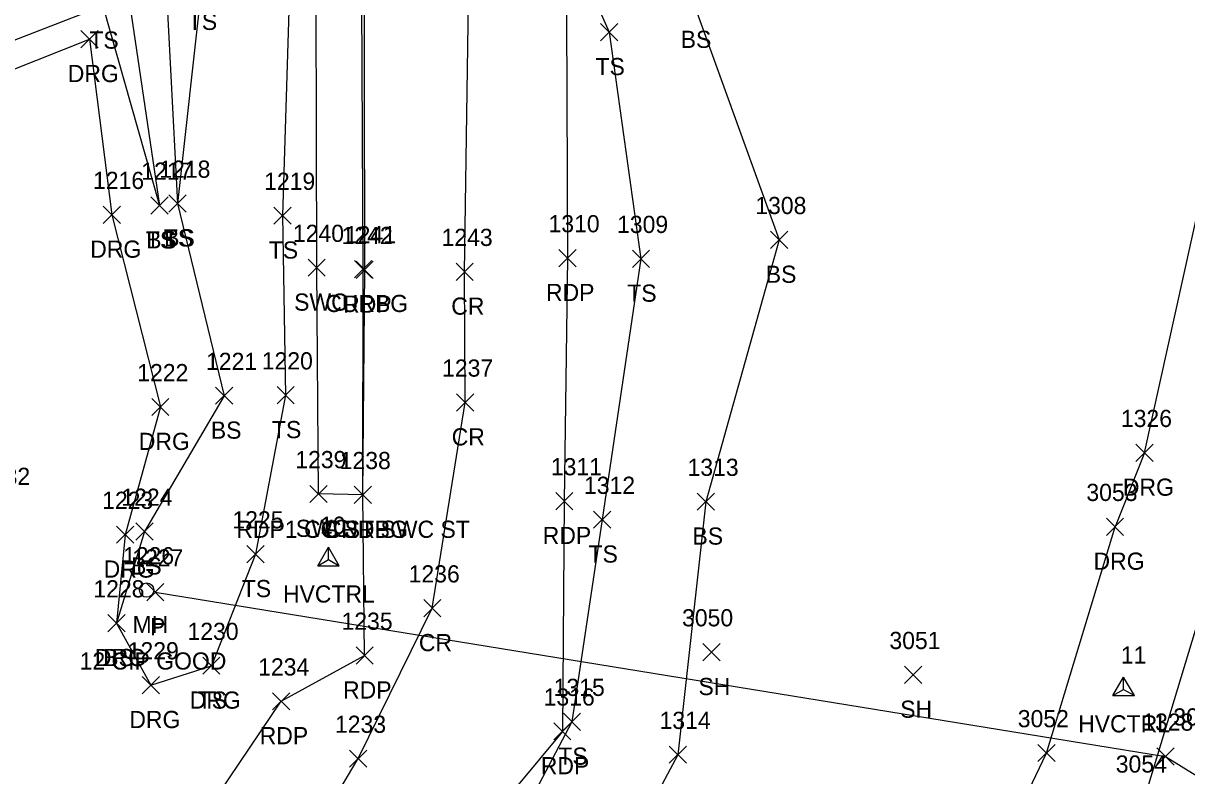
# Model space of a CAD drawing. Extents: x 49137 to 50946, y 9590 to 10709.
# Drawn here: x 49926.3 to 50061.8, y 9806.1 to 9893.7 of the extents above; entities that cross this region are included whole.
import ezdxf

# ---------------------------------------------------------------- set-up
doc = ezdxf.new("R2010")
doc.units = 0
for name, color, linetype in [('C_A', 7, 'Continuous'), ('C_I', 7, 'Continuous'), ('CPSM', 7, 'Continuous'), ('D_A', 7, 'Continuous'), ('D_C', 7, 'Continuous'), ('D_I', 7, 'Continuous'), ('D_TIC', 7, 'Continuous'), ('DCP', 7, 'Continuous'), ('L_A', 7, 'Continuous'), ('L_I', 7, 'Continuous'), ('L_TIC', 7, 'Continuous'), ('LELB', 7, 'Continuous'), ('P_A', 7, 'Continuous'), ('P_I', 7, 'Continuous'), ('P_TIC', 7, 'Continuous'), ('PET', 7, 'Continuous'), ('PRC', 7, 'Continuous'), ('R_A', 7, 'Continuous'), ('R_I', 7, 'Continuous'), ('R_TIC', 7, 'Continuous'), ('RC', 7, 'Continuous'), ('RDG', 7, 'Continuous'), ('RSW', 7, 'Continuous'), ('U_A', 7, 'Continuous'), ('U_I', 7, 'Continuous'), ('UUMH', 7, 'Continuous')]:
    doc.layers.add(name, color=color, linetype=linetype)

msp = doc.modelspace()

# ---------------------------------------------------------------- linework, layer by layer
at = {"layer": 'CPSM'}
for p, q in [((49960.61, 9830.56), (49961.86, 9832.72)), ((49963.11, 9830.56), (49961.86, 9832.72)), ((49961.86, 9831.28), (49961.86, 9832.72)), ((49960.61, 9830.56), (49961.86, 9831.28)), ((49960.61, 9830.56), (49963.11, 9830.56)), ((49961.86, 9831.28), (49961.86, 9831.28)), ((49961.86, 9831.28), (49963.11, 9830.56)), ((50053.22, 9815.45), (50054.47, 9817.61)), ((50055.72, 9815.45), (50054.47, 9817.61)), ((50054.47, 9816.17), (50054.47, 9817.61)), ((50053.22, 9815.45), (50054.47, 9816.17)), ((50054.47, 9816.17), (50054.47, 9816.17)), ((50054.47, 9816.17), (50055.72, 9815.45)), ((50053.22, 9815.45), (50055.72, 9815.45))]:
    msp.add_line(p, q, dxfattribs=at)
at = {"layer": 'D_TIC'}
for points in [[(49940.69, 9826.48), (49942.69, 9828.48)], [(49942.69, 9826.48), (49940.69, 9828.48)], [(50058.34, 9807.37), (50060.34, 9809.37)], [(50060.34, 9807.37), (50058.34, 9809.37)]]:
    msp.add_lwpolyline(points, dxfattribs=at)
at = {"layer": 'DCP'}
msp.add_lwpolyline([(49941.69, 9827.48), (50059.34, 9808.37), (50181.4, 9733.09), (50281.74, 9743.29), (50422.72, 9892.52), (50122.34, 10663.61), (50179.93, 10552.61), (50179.64, 10394.45), (50122.34, 10285.07), (50121.56, 10284.35)], dxfattribs=at)
at = {"layer": 'L_TIC'}
for points in [[(49993.55, 9891.66), (49995.55, 9893.66)], [(49995.55, 9891.66), (49993.55, 9893.66)], [(49941.19, 9871.49), (49943.19, 9873.49)], [(49943.19, 9871.49), (49941.19, 9873.49)], [(49941.19, 9871.49), (49943.19, 9873.49)], [(49943.19, 9871.49), (49941.19, 9873.49)], [(49943.28, 9871.72), (49945.28, 9873.72)], [(49945.28, 9871.72), (49943.28, 9873.72)], [(49943.28, 9871.72), (49945.28, 9873.72)], [(49945.28, 9871.72), (49943.28, 9873.72)], [(49955.5, 9870.31), (49957.5, 9872.31)], [(49957.5, 9870.31), (49955.5, 9872.31)], [(50013.35, 9867.49), (50015.35, 9869.49)], [(50015.35, 9867.49), (50013.35, 9869.49)], [(49997.25, 9865.29), (49999.25, 9867.29)], [(49999.25, 9865.29), (49997.25, 9867.29)], [(49948.72, 9849.35), (49950.72, 9851.35)], [(49950.72, 9849.35), (49948.72, 9851.35)], [(49955.87, 9849.41), (49957.87, 9851.41)], [(49957.87, 9849.41), (49955.87, 9851.41)], [(50004.81, 9837.02), (50006.81, 9839.02)], [(50006.81, 9837.02), (50004.81, 9839.02)], [(49992.74, 9834.93), (49994.74, 9836.93)], [(49994.74, 9834.93), (49992.74, 9836.93)], [(49939.43, 9833.54), (49941.43, 9835.54)], [(49941.43, 9833.54), (49939.43, 9835.54)], [(49952.36, 9830.91), (49954.36, 9832.91)], [(49954.36, 9830.91), (49952.36, 9832.91)], [(49936.17, 9822.88), (49938.17, 9824.88)], [(49938.17, 9822.88), (49936.17, 9824.88)], [(50005.46, 9819.51), (50007.46, 9821.51)], [(50007.46, 9819.51), (50005.46, 9821.51)], [(49947.22, 9817.93), (49949.22, 9819.93)], [(49949.22, 9817.93), (49947.22, 9819.93)], [(50028.96, 9816.87), (50030.96, 9818.87)], [(50030.96, 9816.87), (50028.96, 9818.87)], [(49989.22, 9811.41), (49991.22, 9813.41)], [(49991.22, 9811.41), (49989.22, 9813.41)], [(50001.54, 9807.57), (50003.54, 9809.57)], [(50003.54, 9807.57), (50001.54, 9809.57)]]:
    msp.add_lwpolyline(points, dxfattribs=at)
at = {"layer": 'LELB'}
for points in [[(49958.48, 9981.57), (49957.46, 9951.84), (49957.85, 9930.61), (49957.54, 9905.22), (49956.5, 9871.31), (49956.87, 9850.41), (49953.36, 9831.91), (49948.22, 9818.93)], [(49957.46, 9951.84), (49951.78, 9931.22), (49944.71, 9910.62), (49943.73, 9906.36), (49944.54, 9903.18), (49942.9, 9898.76), (49944.28, 9872.72), (49949.72, 9850.35), (49940.43, 9834.54), (49937.17, 9823.88)], [(49944.71, 9910.62), (49946.87, 9905.57), (49947.07, 9897.92), (49944.28, 9872.72)], [(49989.55, 9904), (49994.55, 9892.66), (49998.25, 9866.29), (49993.74, 9835.93), (49990.22, 9812.41), (49973.48, 9780.67)], [(49989.55, 9904), (50004.44, 9895.83), (50014.35, 9868.49), (50005.81, 9838.02), (50002.54, 9808.57), (49984.2, 9774.21)], [(49673.66, 9797.9), (49709.15, 9811.52), (49739.95, 9820.62), (49781.06, 9838.09), (49823.28, 9856.66), (49863.52, 9873.12), (49910.58, 9889.54), (49938.11, 9900.03), (49942.19, 9872.49)], [(49675.72, 9793.72), (49710.88, 9807.74), (49741.07, 9817.58), (49781.98, 9836.04), (49824.42, 9852.68), (49865.21, 9869.56), (49911.79, 9886.53), (49935.6, 9895.74), (49942.19, 9872.49)], [(49918.74, 9626.48), (49955.93, 9659.04), (50003.73, 9703.66), (50024.34, 9743.65), (50032.96, 9768.3), (50056.89, 9803.49), (50065.96, 9833.31)]]:
    msp.add_lwpolyline(points, dxfattribs=at)
at = {"layer": 'P_TIC'}
for points in [[(49988.7, 9865.37), (49990.7, 9867.37)], [(49990.7, 9865.37), (49988.7, 9867.37)], [(49965.08, 9864), (49967.08, 9866)], [(49967.08, 9864), (49965.08, 9866)], [(49976.72, 9863.78), (49978.72, 9865.78)], [(49978.72, 9863.78), (49976.72, 9865.78)], [(49976.78, 9848.57), (49978.78, 9850.57)], [(49978.78, 9848.57), (49976.78, 9850.57)], [(49964.86, 9837.81), (49966.86, 9839.81)], [(49966.86, 9837.81), (49964.86, 9839.81)], [(49988.32, 9837.09), (49990.32, 9839.09)], [(49990.32, 9837.09), (49988.32, 9839.09)], [(49972.95, 9824.62), (49974.95, 9826.62)], [(49974.95, 9824.62), (49972.95, 9826.62)], [(49965.07, 9819.11), (49967.07, 9821.11)], [(49967.07, 9819.11), (49965.07, 9821.11)], [(49955.36, 9813.79), (49957.36, 9815.79)], [(49957.36, 9813.79), (49955.36, 9815.79)], [(49988.1, 9810.29), (49990.1, 9812.29)], [(49990.1, 9810.29), (49988.1, 9812.29)], [(49964.31, 9807.12), (49966.31, 9809.12)], [(49966.31, 9807.12), (49964.31, 9809.12)]]:
    msp.add_lwpolyline(points, dxfattribs=at)
at = {"layer": 'PET'}
msp.add_lwpolyline([(49941.82, 9793.28), (49956.36, 9814.79), (49966.07, 9820.11), (49965.86, 9838.81), (49966.08, 9865), (49966, 9911.87), (49965.71, 9947.75), (49965.49, 9981.09), (49977.22, 9981.69), (49989.03, 9982.19), (49989.41, 9973.23), (49989.05, 9951.58), (49989.55, 9915.93), (49989.55, 9904), (49989.7, 9866.37), (49989.32, 9838.09), (49989.1, 9811.29), (49967.49, 9785.27)], dxfattribs=at)
at = {"layer": 'PRC'}
msp.add_lwpolyline([(49953.02, 9787.37), (49965.31, 9808.12), (49973.95, 9825.62), (49977.78, 9849.57), (49977.72, 9864.78), (49978.39, 9912), (49976.86, 9948.04), (49977.22, 9981.69)], dxfattribs=at)
at = {"layer": 'R_TIC'}
for points in [[(49933.02, 9890.85), (49935.02, 9892.85)], [(49935.02, 9890.85), (49933.02, 9892.85)], [(49935.62, 9870.41), (49937.62, 9872.41)], [(49937.62, 9870.41), (49935.62, 9872.41)], [(49959.49, 9864.25), (49961.49, 9866.25)], [(49961.49, 9864.25), (49959.49, 9866.25)], [(49964.9, 9864.09), (49966.9, 9866.09)], [(49966.9, 9864.09), (49964.9, 9866.09)], [(49941.28, 9848.04), (49943.28, 9850.04)], [(49943.28, 9848.04), (49941.28, 9850.04)], [(50055.89, 9842.71), (50057.89, 9844.71)], [(50057.89, 9842.71), (50055.89, 9844.71)], [(49959.7, 9837.92), (49961.7, 9839.92)], [(49961.7, 9837.92), (49959.7, 9839.92)], [(49964.86, 9837.81), (49966.86, 9839.81)], [(49966.86, 9837.81), (49964.86, 9839.81)], [(49964.86, 9837.81), (49966.86, 9839.81)], [(49966.86, 9837.81), (49964.86, 9839.81)], [(50052.47, 9834.1), (50054.47, 9836.1)], [(50054.47, 9834.1), (50052.47, 9836.1)], [(49937.19, 9833.18), (49939.19, 9835.18)], [(49939.19, 9833.18), (49937.19, 9835.18)], [(49936.17, 9822.88), (49938.17, 9824.88)], [(49938.17, 9822.88), (49936.17, 9824.88)], [(49947.22, 9817.93), (49949.22, 9819.93)], [(49949.22, 9817.93), (49947.22, 9819.93)], [(49940.18, 9815.67), (49942.18, 9817.67)], [(49942.18, 9815.67), (49940.18, 9817.67)], [(50044.48, 9807.77), (50046.48, 9809.77)], [(50046.48, 9807.77), (50044.48, 9809.77)]]:
    msp.add_lwpolyline(points, dxfattribs=at)
at = {"layer": 'RC'}
msp.add_lwpolyline([(49965.86, 9838.81), (49965.9, 9865.09), (49965.65, 9911.91), (49965.35, 9947.97), (49965.18, 9981.1)], dxfattribs=at)
at = {"layer": 'RDG'}
for points in [[(49677.61, 9787.68), (49712.16, 9801.58), (49742.55, 9811.6), (49783.63, 9831.79), (49826.52, 9847.59), (49866.61, 9865.33), (49912.42, 9883.28), (49934.02, 9891.85), (49936.62, 9871.41), (49942.28, 9849.04), (49938.19, 9834.18), (49937.17, 9823.88), (49941.18, 9816.67), (49948.22, 9818.93)], [(50056.89, 9843.71), (50065.07, 9880.71)], [(50056.89, 9843.71), (50053.47, 9835.1)], [(49907.98, 9635.82), (49950.02, 9667.9), (49993.51, 9711.79), (50017.65, 9749.22), (50029.04, 9774.29), (50045.48, 9808.77), (50053.47, 9835.1)]]:
    msp.add_lwpolyline(points, dxfattribs=at)
at = {"layer": 'RSW'}
msp.add_lwpolyline([(49965.86, 9838.81), (49960.7, 9838.92), (49960.49, 9865.25), (49960.39, 9911.74), (49960.12, 9947.64), (49960.2, 9981.3), (49965.18, 9981.1), (49965.49, 9981.09)], dxfattribs=at)
at = {"layer": 'UUMH'}
for p, q in [((49940.68, 9827.73), (49940.68, 9827.73)), ((49941.51, 9827.73), (49941.51, 9827.73))]:
    msp.add_line(p, q, dxfattribs=at)
msp.add_circle((49940.68, 9827.73), 0.833, dxfattribs=at)

# ---------------------------------------------------------------- texts
at = {"layer": 'C_A'}
for p in [(49956.56, 9826.28), (50049.17, 9811.17)]:
    msp.add_text('HVCTRL', height=2, dxfattribs=at).set_placement(p)
at = {"layer": 'C_I'}
for s, p in [('10', (49960.88, 9834.28)), ('11', (50054.14, 9819.17))]:
    msp.add_text(s, height=2, dxfattribs=at).set_placement(p)
at = {"layer": 'D_A'}
msp.add_text('P', height=2, dxfattribs=at).set_placement((49941.07, 9822.48))
at = {"layer": 'D_C'}
msp.add_text('12 CIP GOOD', height=2, dxfattribs=at).set_placement((49932.88, 9818.48))
at = {"layer": 'D_I'}
for s, p in [('1227', (49939, 9830.48)), ('1328', (50056.64, 9811.37)), ('3056', (50060.25, 9811.97))]:
    msp.add_text(s, height=2, dxfattribs=at).set_placement(p)
at = {"layer": 'L_A'}
for s, p in [('TS', (49945.48, 9892.92)), ('TS', (49934.01, 9890.74)), ('BS', (50002.88, 9890.83)), ('TS', (49992.96, 9887.66)), ('TS', (49940.6, 9867.49)), ('BS', (49940.63, 9867.49)), ('TS', (49942.69, 9867.72)), ('BS', (49942.72, 9867.72)), ('TS', (49954.91, 9866.31)), ('BS', (50012.79, 9863.49)), ('TS', (49996.66, 9861.29)), ('BS', (49948.16, 9845.35)), ('TS', (49955.28, 9845.41)), ('BS', (50004.25, 9833.02)), ('TS', (49992.15, 9830.93)), ('BS', (49938.87, 9829.54)), ('TS', (49951.77, 9826.91)), ('BS', (49935.62, 9818.88)), ('SH', (50004.95, 9815.51)), ('TS', (49946.63, 9813.93)), ('SH', (50028.45, 9812.87)), ('TS', (49988.63, 9807.41))]:
    msp.add_text(s, height=2, dxfattribs=at).set_placement(p)
at = {"layer": 'L_I'}
for s, p in [('1217', (49940.06, 9875.49)), ('1217', (49940.06, 9875.49)), ('1218', (49942.16, 9875.72)), ('1218', (49942.16, 9875.72)), ('1219', (49954.37, 9874.31)), ('1308', (50011.57, 9871.49)), ('1309', (49995.47, 9869.29)), ('1221', (49947.6, 9853.35)), ('1220', (49954.09, 9853.41)), ('1313', (50003.68, 9841.02)), ('1132', (49921.17, 9839.97)), ('1312', (49991.62, 9838.93)), ('1224', (49937.74, 9837.54)), ('1225', (49950.67, 9834.91)), ('1228', (49934.48, 9826.88)), ('3050', (50003.04, 9823.51)), ('1230', (49945.44, 9821.93)), ('3051', (50027.19, 9820.87)), ('1315', (49988.09, 9815.41)), ('1314', (50000.42, 9811.57)), ('3054', (50053.55, 9806.49))]:
    msp.add_text(s, height=2, dxfattribs=at).set_placement(p)
at = {"layer": 'P_A'}
for s, p in [('RDP', (49987.19, 9861.37)), ('RDP', (49963.57, 9860)), ('CR', (49976.16, 9859.78)), ('CR', (49976.21, 9844.57)), ('RDP', (49963.35, 9833.81)), ('RDP', (49986.81, 9833.09)), ('CR', (49972.39, 9820.62)), ('RDP', (49963.56, 9815.11)), ('RDP', (49953.85, 9809.79)), ('RDP', (49986.59, 9806.29))]:
    msp.add_text(s, height=2, dxfattribs=at).set_placement(p)
at = {"layer": 'P_I'}
for s, p in [('1310', (49987.49, 9869.37)), ('1242', (49963.39, 9868)), ('1243', (49975.03, 9867.78)), ('1237', (49975.09, 9852.57)), ('1238', (49963.17, 9841.81)), ('1311', (49987.76, 9841.09)), ('1236', (49971.2, 9828.62)), ('1235', (49963.38, 9823.11)), ('1234', (49953.67, 9817.79)), ('1316', (49986.92, 9814.29)), ('1233', (49962.62, 9811.12))]:
    msp.add_text(s, height=2, dxfattribs=at).set_placement(p)
at = {"layer": 'R_A'}
for s, p in [('DRG', (49931.5, 9886.85)), ('DRG', (49934.11, 9866.41)), ('SWC', (49957.86, 9860.25)), ('CURBG', (49961.48, 9860.09)), ('DRG', (49939.77, 9844.04)), ('DRG', (50054.38, 9838.71)), ('RDP1 CG ST SWC ST', (49951.13, 9833.81)), ('SWC', (49958.06, 9833.92)), ('CURBG', (49961.45, 9833.81)), ('DRG', (50050.96, 9830.1)), ('DRG', (49935.68, 9829.18)), ('DRG', (49934.66, 9818.88)), ('DRG', (49945.71, 9813.93)), ('DRG', (49938.67, 9811.67))]:
    msp.add_text(s, height=2, dxfattribs=at).set_placement(p)
at = {"layer": 'R_I'}
for s, p in [('1216', (49934.44, 9874.41)), ('1240', (49957.72, 9868.25)), ('1241', (49963.77, 9868.09)), ('1222', (49939.59, 9852.04)), ('1326', (50054.15, 9846.71)), ('1239', (49958, 9841.92)), ('1238', (49963.17, 9841.81)), ('1238', (49963.17, 9841.81)), ('3053', (50050.13, 9838.1)), ('1223', (49935.5, 9837.18)), ('1228', (49934.48, 9826.88)), ('1230', (49945.44, 9821.93)), ('1229', (49938.48, 9819.67)), ('3052', (50042.14, 9811.77))]:
    msp.add_text(s, height=2, dxfattribs=at).set_placement(p)
at = {"layer": 'U_A'}
msp.add_text('MH', height=2, dxfattribs=at).set_placement((49939.04, 9822.73))
at = {"layer": 'U_I'}
msp.add_text('1226', height=2, dxfattribs=at).set_placement((49937.93, 9830.73))

doc.saveas('drawing.dxf')
